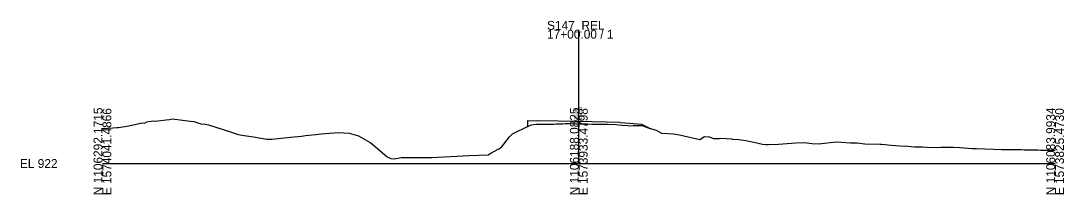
# Model space of a CAD drawing. Extents: x 1557985 to 1558314, y 1113650 to 1118205.
# Drawn here: x 1557985.4 to 1558314, y 1115150.1 to 1115204.9 of the extents above; entities that cross this region are included whole.
import ezdxf

# ---------------------------------------------------------------- set-up
doc = ezdxf.new("R2010")
doc.units = 0
for name, color, linetype in [('RD_GPK_XS_Cell', 7, 'Continuous'), ('RD_XS_EarthShd', 7, 'Continuous'), ('RD_XS_ExGround', 7, 'Continuous'), ('RD_XS_Pave', 7, 'Continuous'), ('RD_XS_TieSlope', 7, 'Continuous'), ('RD_XS_TX_Elev_EX', 7, 'Continuous'), ('RD_XS_TX_Elev_PR', 7, 'Continuous')]:
    doc.layers.add(name, color=color, linetype=linetype)

msp = doc.modelspace()

# ---------------------------------------------------------------- linework, layer by layer
at = {"layer": 'RD_GPK_XS_Cell'}
for p, q in [((1558161.13, 1115159.8), (1558161.13, 1115202.04)), ((1558011.13, 1115159.8), (1558161.13, 1115159.8)), ((1558161.13, 1115159.8), (1558311.13, 1115159.8))]:
    msp.add_line(p, q, dxfattribs=at)
at = {"layer": 'RD_XS_EarthShd'}
for p, q in [((1558145.12, 1115173.35), (1558148.13, 1115173.29)), ((1558174.13, 1115172.77), (1558177.13, 1115172.53)), ((1558177.13, 1115172.53), (1558180.88, 1115172.23))]:
    msp.add_line(p, q, dxfattribs=at)
at = {"layer": 'RD_XS_ExGround'}
msp.add_lwpolyline([(1558011.13, 1115170.9), (1558014.4, 1115171.03), (1558015.64, 1115171.14), (1558016.13, 1115171.22), (1558019.46, 1115171.65), (1558023.63, 1115172.61), (1558024.33, 1115172.54), (1558025.14, 1115172.96), (1558027.08, 1115173.31), (1558027.75, 1115173.15), (1558031.23, 1115173.6), (1558032.28, 1115173.72), (1558033.09, 1115173.88), (1558038.85, 1115173.15), (1558039.86, 1115173.08), (1558042.12, 1115172.38), (1558043.44, 1115172.19), (1558044.56, 1115172.04), (1558049.41, 1115170.42), (1558051.81, 1115169.66), (1558052.62, 1115169.38), (1558053.88, 1115168.97), (1558055.8, 1115168.62), (1558058.72, 1115168.18), (1558062.87, 1115167.5), (1558063.59, 1115167.44), (1558064.43, 1115167.49), (1558070.37, 1115168.11), (1558073.78, 1115168.4), (1558075.08, 1115168.64), (1558076.13, 1115168.8), (1558078.29, 1115168.95), (1558079.96, 1115169.14), (1558085.42, 1115169.64), (1558088.77, 1115169.34), (1558091.75, 1115168.51), (1558095.48, 1115166.41), (1558096.24, 1115165.78), (1558100.74, 1115161.93), (1558101.94, 1115161.39), (1558103.04, 1115161.28), (1558105.16, 1115161.72), (1558114.81, 1115161.74), (1558126.63, 1115162.32), (1558132.63, 1115162.49), (1558133.47, 1115163.07), (1558135.93, 1115164.41), (1558136.76, 1115164.96), (1558139.33, 1115168.27), (1558140.28, 1115169.15), (1558141.5, 1115169.82), (1558146.1, 1115171.99), (1558147.69, 1115172.26), (1558148.69, 1115172.25), (1558151.47, 1115172.28), (1558153.29, 1115172.28), (1558153.85, 1115172.29), (1558155.59, 1115172.37), (1558155.97, 1115172.38), (1558156.8, 1115172.41), (1558158.51, 1115172.44), (1558160.45, 1115172.38), (1558161.13, 1115172.37), (1558162.06, 1115172.36), (1558162.75, 1115172.34), (1558163.91, 1115172.29), (1558165.28, 1115172.23), (1558165.87, 1115172.22), (1558169.7, 1115172.22), (1558170.21, 1115172.22), (1558172.83, 1115172.13), (1558174.84, 1115171.9), (1558176.47, 1115171.81), (1558177.06, 1115171.73), (1558178.24, 1115171.78), (1558181.11, 1115171.81), (1558183.02, 1115171.03), (1558185.53, 1115170.36), (1558187.21, 1115169.4), (1558190.98, 1115169.21), (1558192.23, 1115168.98), (1558192.85, 1115168.88), (1558199.29, 1115167.38), (1558200.75, 1115168.3), (1558202.17, 1115168.2), (1558203.57, 1115167.72), (1558205.4, 1115167.75), (1558205.86, 1115167.77), (1558209.18, 1115167.56), (1558209.49, 1115167.53), (1558211.55, 1115167.35), (1558213.74, 1115167.07), (1558216.3, 1115166.51), (1558218.96, 1115165.9), (1558220.04, 1115165.81), (1558220.86, 1115165.85), (1558223.99, 1115165.95), (1558225.42, 1115166.05), (1558229.52, 1115166.34), (1558232.25, 1115166.4), (1558234.54, 1115166.11), (1558236.58, 1115166.05), (1558242.13, 1115166.64), (1558243.83, 1115166.54), (1558246.64, 1115166.3), (1558248.83, 1115166.38), (1558251.16, 1115166), (1558255.89, 1115165.92), (1558256.42, 1115165.89), (1558259.51, 1115165.64), (1558262.2, 1115165.41), (1558264.79, 1115165.23), (1558266.87, 1115165.11), (1558269.34, 1115165.02), (1558272.12, 1115164.9), (1558275.19, 1115164.95), (1558278.11, 1115164.99), (1558279.15, 1115164.95), (1558281.08, 1115164.82), (1558283.64, 1115164.64), (1558285.11, 1115164.54), (1558285.47, 1115164.52), (1558286.41, 1115164.5), (1558289.15, 1115164.41), (1558294.32, 1115164.21), (1558294.65, 1115164.2), (1558296.22, 1115164.18), (1558297.26, 1115164.2), (1558298.59, 1115164.18), (1558300.45, 1115164.18), (1558301.38, 1115164.14), (1558303.28, 1115164.1), (1558305.73, 1115164.08), (1558306.57, 1115164.06), (1558307.92, 1115164.05), (1558310.13, 1115164.04), (1558311.13, 1115164.02)], dxfattribs=at)
at = {"layer": 'RD_XS_Pave'}
for p, q in [((1558161.13, 1115173.03), (1558148.13, 1115173.29)), ((1558174.13, 1115172.77), (1558161.13, 1115173.03))]:
    msp.add_line(p, q, dxfattribs=at)
at = {"layer": 'RD_XS_TieSlope'}
for p, q in [((1558145.12, 1115171.53), (1558145.12, 1115173.35)), ((1558180.88, 1115172.23), (1558183.56, 1115170.89))]:
    msp.add_line(p, q, dxfattribs=at)

# ---------------------------------------------------------------- texts
at = {"layer": 'RD_GPK_XS_Cell'}
for s, p in [('S147_REL', (1558151.13, 1115202.04)), ('17+00.00 / 1', (1558151.13, 1115199.24)), ('EL 922', (1557985.13, 1115158.4))]:
    msp.add_text(s, height=2.8, dxfattribs=at).set_placement(p)
for s, p in [('N 1106292.1715', (1558011.13, 1115149.8)), ('E 1574041.4866', (1558013.93, 1115149.8)), ('N 1106188.0825', (1558161.13, 1115149.8)), ('E 1573933.4798', (1558163.93, 1115149.8)), ('N 1106083.9934', (1558311.13, 1115149.8)), ('E 1573825.4730', (1558313.93, 1115149.8))]:
    msp.add_text(s, height=2.8, rotation=90, dxfattribs=at).set_placement(p)
at = {"layer": 'RD_XS_TX_Elev_EX'}
msp.add_text('934.58', height=1, rotation=90, dxfattribs=at).set_placement((1558160.63, 1115172.87))
at = {"layer": 'RD_XS_TX_Elev_PR'}
msp.add_text(' 935.24', height=1, rotation=90, dxfattribs=at).set_placement((1558162.13, 1115173.03))

doc.saveas('drawing.dxf')
